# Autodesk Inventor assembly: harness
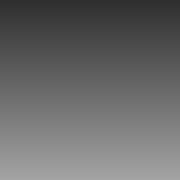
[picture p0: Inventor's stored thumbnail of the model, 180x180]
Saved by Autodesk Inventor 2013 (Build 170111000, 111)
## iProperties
HarnessSettings: <HarnessSettings><Defaults><Segments><Diameter value="0.200 in" fromwires="True"/><Offset value="0.100 in"/><ColorStyle value="Blue"/><BendRadius value="19" fro
Control State: 0
Master: False
Checked Out: False
Part Number: harness
Document SubType Name: Assembly
Shininess: 64.0
Length Units: 11272
Angle Units: 11279
Time Units: 11290
Mass Units: 11286
Length Display Precision: 3
Angle Display Precision: 2
Compacted: True
Density: 0.0
Volumn: 0.0
Area: 0.0
PropertySet Name: Model Information
HarnessSettings: <HarnessSettings><Defaults><Segments><Diameter value="0.200 in" fromwires="True"/><Offset value="0.100 in"/><ColorStyle value="Blau"/><RoundUp value=""/><BendRa
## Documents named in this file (1)
- C:\Users\wade\Desktop\Neuer Ordner\harness.iam
